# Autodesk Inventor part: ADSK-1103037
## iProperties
Shininess: 41.0
Length Units: 11272
Angle Units: 11279
Time Units: 11290
Mass Units: 11286
Length Display Precision: 4
Angle Display Precision: 2
Compacted: True
Created: 2000-08
Part Number: ADSK-1103037
Document SubType Name: Modeling
Description: COUPLING - SIDE
Mass: 3.73403 g
Surface Area: 29.9497 cm^2
Volume: 2.98722 cm^3
Density: 1.25 g/cm^3
Material: Silicone
Density: 0.0
Volumn: 0.0
Area: 0.0
PropertySet Name: Model Information
Control State: 0
Master: False
Checked Out: False
Author: Autodesk, Inc.
